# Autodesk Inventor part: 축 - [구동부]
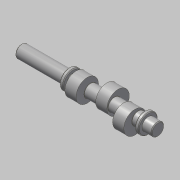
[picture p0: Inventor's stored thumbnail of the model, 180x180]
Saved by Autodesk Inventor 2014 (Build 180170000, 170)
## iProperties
Company: 한국ATC센터
Created: 2014-08
Part Number: 축 - [구동부]
Document SubType Name: Modeling
Designer: mdu
Density: 7.86 g/cm^3
Material: 강철, 연강
Mass: 516.584 g
Surface Area: 162.515 cm^2
Volume: 65.7231 cm^3
Appearance: 강철
Author: mdu
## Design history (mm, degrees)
sketch "스케치1"
  geometry: L1 (-91.5, 0)-(91.5, 0); L2 (-91.5, 0)-(-91.5, 8.5); L3 (-91.5, 8.5)-(-27.5, 8.5); L4 (-27.5, 8.5)-(-27.5, 13); L5 (-27.5, 13)-(-22.5, 13); L6 (-22.5, 13)-(-22.5, 8.5); L7 (-22.5, 8.5)-(73.5, 8.5); L8 (73.5, 8.5)-(73.5, 13); L9 (73.5, 13)-(78.5, 13); L10 (78.5, 13)-(78.5, 8.5); L11 (78.5, 8.5)-(91.5, 8.5); L12 (91.5, 8.5)-(91.5, 0); 2 further points
  constraints: 24 end point, 5 parallel, 1 coincident, 1 horizontal, 1 midpoint, 1 perpendicular
  dimensions: "d0" = 183 distance of L1.start L1.end (derived); "d2" = 17 diameter of L3 L1; "d3" = 26 diameter of L5 L1; "d4" = 17 diameter of L7 L1; "d5" = 26 diameter of L9 L1; "d6" = 17 diameter of L11 L1; "d7" = 5 distance of L8.end L9.end; "d8" = 5 distance of L4.end L5.end; "d10" = 64 distance of L2.end L3.end; "d11" = 13 distance of L10.end L11.end; "d35" = 96 distance between parallel lines of L8 L6
revolve "회전1" sketch "스케치1" stored, may be unused: angle "d12" = 90 deg
node "작업 평면7"
sketch "스케치6"
  geometry: C1 r 15 at (0, 5); 1 further point
  constraints: 1 centre point, 1 vertical alignment
  dimensions: "d37" = 30 diameter of C1; "d38" = 5 distance of C1.centre point (0, 0)
extrude "돌출4" join sketch "스케치6" stored distance "d33" = 15; taper "d34" = 0 deg
node "작업 평면8"
sketch "스케치7"
  geometry: L1 (0, 0)-(-6.5, -11.258); L2 (0, 0)-(13, 0); C1 r 15 at (-2.5, -4.33); A1 r 13 centre (0, 0) between (-6.5, -11.258) and (13, 0) reference; 1 further point
  constraints: 4 end point, 2 point on circle, 1 centre point, 1 horizontal, 1 point on line
  dimensions: "d40" = 120 deg angle of L1 L2; "d41" = 30 diameter of C1; "d42" = 5 distance of point (0, 0) C1.centre
extrude "돌출5" join sketch "스케치7" stored distance "d43" = 15; taper "d44" = 0 deg
node "작업 평면9"
sketch "스케치8"
  geometry: L1 (0, 0)-(4.25, -7.361); L2 (0, 0)-(-8.5, 0); C1 r 15 at (2.5, -4.33); A1 r 8.5 centre (0, 0) between (4.25, -7.361) and (-8.5, 0) reference; 1 further point
  constraints: 4 end point, 2 point on circle, 1 centre point, 1 horizontal, 1 point on line
  dimensions: "d46" = 120 deg angle of L1 L2; "d47" = 30 diameter of C1; "d48" = 5 distance of point (0, 0) C1.centre
extrude "돌출6" join sketch "스케치8" stored distance "d49" = 15; taper "d50" = 0 deg
node "작업 평면3"
sketch "스케치5"
  geometry: L1 (32, 8.5)-(32, -8.5) reference; L2 (27.5, -2.5)-(14.5, -2.5); L3 (14.5, 2.5)-(27.5, 2.5); A1 r 2.5 centre (14.5, 0) between (14.5, 2.5) and (14.5, -2.5); A2 r 2.5 centre (27.5, 0) between (27.5, -2.5) and (27.5, 2.5); 4 further points
  constraints: 4 end point, 4 point on circle, 4 tangent, 2 centre point, 2 point on line, 1 horizontal alignment, 1 midpoint, 1 parallel, 1 perpendicular
  dimensions: "d23" = 5 distance between parallel lines of L3 L2; "d36" = 20 dimension on A1 L1; "d52" = 2 distance edge to line of A2 L1
extrude "돌출3" cut sketch "스케치5" distance "d25" = 3; taper "d26" = 0 deg
chamfer "모따기1" distance "d27" = 1; stored, may be unused: second distance "d28" = 2, angle "d29" = 45 deg
fillet "모깎기1" dims "d51" = 0.3
chamfer "모따기2" distance "d53" = 1; stored, may be unused: second distance "d54" = 2, angle "d55" = 45 deg
node "작업 평면10"
node "솔리드1"
other parameters: "d39" = -32, "d45" = 32
